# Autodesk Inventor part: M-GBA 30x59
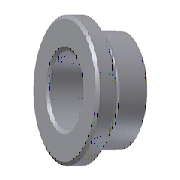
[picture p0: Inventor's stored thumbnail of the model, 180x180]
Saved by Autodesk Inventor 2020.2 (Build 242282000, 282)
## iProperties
Created: 2019-01
Part Number: M-GBA 30x59
Material: SUJ 2
Description: TULEJA PROWADZĄCA
Document SubType Name: Modeling
Designer: F.Stasiak
Standard Revision: 1
Manufacturer: FUTABA
Language: pl-PL
Size Designation: 30x59
Categories: <MemberInstance><Categories><Category DisplayName="Forma wtryskowa" InternalName="349578f2-f4d4-4954-8c09-8e99297a61c0" Mnemonic="MOLD"><Category DisplayName="K
Density: 7.85 g/cm^3
Appearance: Domyślna
Catalog Web Link: www.expertbooks.pl
Manager: www.cadconsulting.pl
Company: Fabian Stasiak CAD Consulting
IsCustomPart: 0
Author: F.Stasiak
Subject: Zbiór ćwiczeń. Autodesk Inventor 2020. Kurs Professional
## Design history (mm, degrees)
body "Solid1"
revolve "Obrót1" stored, may be unused: angle "d13" = 90 deg
revolve "Obrót2" stored, may be unused: angle "d23" = 90 deg
chamfer "Faza1" distance "d24" = 0.5; stored, may be unused: second distance "d25" = 2, angle "d26" = 45 deg
fillet "Zaokrąglenie1" dims "d27" = 0.3
fillet "Zaokrąglenie2" dims "d28" = 0.8
sketch "Sketch1"
  geometry: L1 (0, -16.2)-(0, 6.2) reference; L2 (0, 10)-(23.5, 10); L3 (23.5, 10)-(23.5, 0); L4 (23.5, 0)-(20.5, 0); L5 (20.5, 0)-(20.5, -2); L6 (20.5, -2)-(21, -2); L7 (21, -2)-(21, -46); L8 (21, -46)-(20.75, -46); L9 (20.75, -46)-(20.75, -49); L10 (20.75, -49)-(0, -49); 1 further point
  constraints: 18 end point, 4 perpendicular, 2 parallel, 2 point on line, 1 horizontal alignment
  dimensions: "d0" = 59 distance between parallel lines of L10 L2 (= B); "d2" = 10 distance between parallel lines of L4 L2 (= T1); "d3" = 42 diameter of L7 L1 (= D); "d4" = 3 distance between parallel lines of L10 L8; "d5" = 41.5 diameter of L9 L1 (= D_Guide); "d6" = 47 diameter of L3 L1 (= D2); "d7" = 0.5 distance between parallel lines of L7 L5; "d8" = 2 distance between parallel lines of L4 L6
sketch "Sketch2"
  geometry: L1 (-20.75, -49)-(20.75, -49) reference; L2 (0, -20.2)-(0, 30.2) reference; L3 (15, 10)-(15, -49); L4 (15, 10)-(15.25, 10); L5 (15.25, 10)-(15.25, 69); L6 (15.25, 69)-(0, 69); L7 (15, -49)-(0, -49); L8 (0, 69)-(0, -49)
  constraints: 12 end point, 3 perpendicular, 3 point on line, 1 collinear, 1 midpoint, 1 parallel
  dimensions: "d18" = 30 diameter of L3 L2 (= d_); "d20" = 59 distance between parallel lines of L1 L4 (= L1); "d21" = 59 distance between parallel lines of L4 L6 (= B); "d22" = 30.5 diameter of L5 L2 (= d1)
other parameters: "d_" = 30 [user parameter; used in 1 equation term], "d1" = 30.5 [user parameter; used in 1 equation term], "L1" = 59 [user parameter; used in 1 equation term], "D" = 42 [user parameter; used in 1 equation term], "D2" = 47 [user parameter; used in 1 equation term], "B" = 59 [user parameter; used in 2 equation terms], "T1" = 10 [user parameter; used in 1 equation term], "D_Guide" = 41.5 [user parameter; used in 1 equation term], "d29" = 0, "d30" = 0, "d31" = 0
